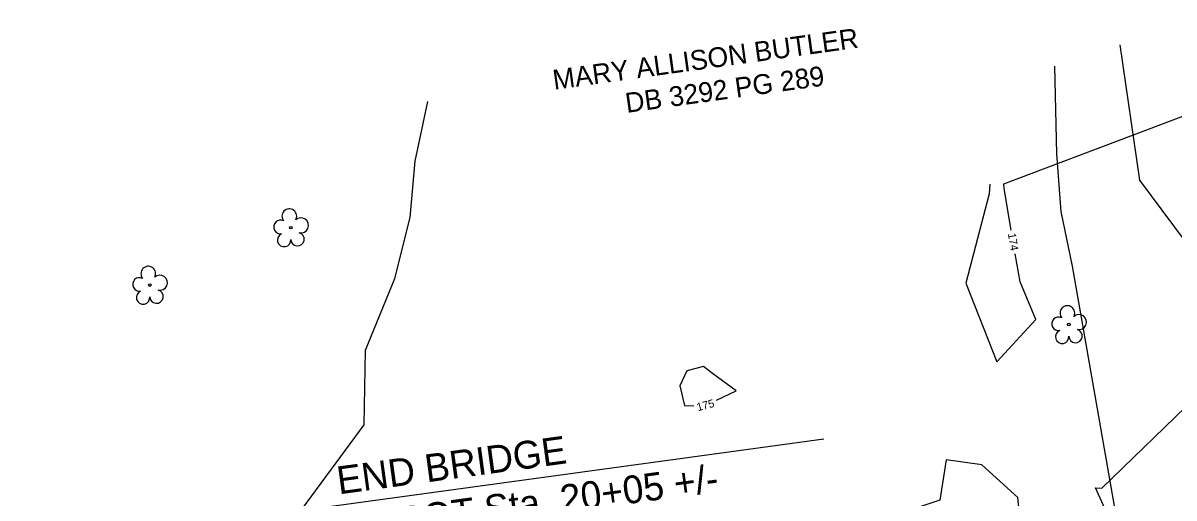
# Model space of a CAD drawing. Extents: x 2086416 to 2115205, y 575507 to 632762.
# Drawn here: x 2112066 to 2112356.1, y 581852.1 to 581971.8 of the extents above; entities that cross this region are included whole.
import ezdxf

# ---------------------------------------------------------------- set-up
doc = ezdxf.new("R2010")
doc.units = 0
for name, color, linetype in [('DTM Contours Major', 7, 'Continuous'), ('DTM Contours Major Text', 7, 'Continuous'), ('DTM Contours Minor', 7, 'Continuous'), ('DTM Contours Minor Text', 7, 'Continuous'), ('Exist Hydro Stream or Body of Water', 7, 'Continuous'), ('Exist Hydro Stream or Body of Water Text', 7, 'Continuous'), ('Exist Property Deed Book Text', 7, 'Continuous'), ('Exist Property Owner Text', 7, 'Continuous'), ('Exist Vegetation Tree CELL', 7, 'Continuous'), ('Exist Vegetation Woods Line', 7, 'Continuous'), ('Prop Horizontal Alignment Station Label', 7, 'Continuous')]:
    doc.layers.add(name, color=color, linetype=linetype)

# ---------------------------------------------------------------- blocks, each defined once
blk = doc.blocks.new('EXIST VEGETATION TREE')
at = {"layer": 'Exist Vegetation Tree CELL'}
blk.add_line((0, 0), (0, 0), dxfattribs=at)
blk.add_circle((0, 0), 0.00652, dxfattribs=at)
for centre, radius, start, end in [((-0.0077, 0.0575), 0.0371, 330.16508, 219.71335), ((-0.0521, 0.0031), 0.0345, 62.66361, 279.3457), ((0.051, 0.0118), 0.038, 257.1011, 134.19993), ((-0.0341, -0.0624), 0.0338, 111.56708, 6.23104), ((0.0335, -0.058), 0.034, 181.28216, 74.55999)]:
    blk.add_arc(centre, radius, start, end, dxfattribs=at)

msp = doc.modelspace()

# ---------------------------------------------------------------- linework, layer by layer
at = {"layer": 'DTM Contours Major'}
for points in [[(2112239.77, 581883.48), (2112237.54, 581885.22), (2112233.31, 581884.15), (2112231.58, 581880.32), (2112232.74, 581875.35), (2112235.11, 581875.27)], [(2112240.76, 581876.76), (2112245.72, 581879.1), (2112239.77, 581883.48)], [(2112307.63, 581860.46), (2112298.69, 581861.68), (2112297.08, 581851.5), (2112289.78, 581849.11), (2112291.03, 581843.54), (2112279.58, 581824.63), (2112299.71, 581826.22), (2112319.48, 581829.38), (2112318.75, 581834.28)], [(2112317.96, 581840.23), (2112316.72, 581852.2), (2112307.63, 581860.46)]]:
    msp.add_lwpolyline(points, dxfattribs=at)
at = {"layer": 'DTM Contours Minor'}
for points in [[(2112315.08, 581919.53), (2112313.29, 581930.07), (2112313.19, 581931.24), (2112370.35, 581952.85)], [(2112309.71, 581931.19), (2112309.53, 581928.69), (2112303.62, 581906.17), (2112311.46, 581886.42), (2112321.28, 581897.08), (2112317.29, 581906.53), (2112316.08, 581913.62)], [(2112254.07, 581816.2), (2112270.16, 581818.14), (2112276.22, 581818.7), (2112299.96, 581821.57), (2112307.56, 581822.62), (2112329.58, 581826.32), (2112343.62, 581828.68), (2112345.41, 581828.91), (2112345.86, 581828.8), (2112351.13, 581828.16), (2112351.3, 581828.82), (2112352.42, 581829.9), (2112349.84, 581834.07), (2112347.16, 581839.69), (2112345.41, 581840.74), (2112341.86, 581842.42), (2112341.8, 581842.53), (2112336.33, 581854.64), (2112337.93, 581854.53), (2112361.72, 581877.6), (2112365.19, 581879.81), (2112375.59, 581882.41), (2112386.63, 581894.46), (2112387.61, 581897.62)]]:
    msp.add_lwpolyline(points, dxfattribs=at)
at = {"layer": 'Exist Hydro Stream or Body of Water'}
for points in [[(2112342.28, 581843.38), (2112330.53, 581910.52), (2112327.68, 581924.24), (2112326.53, 581938.77), (2112326.09, 581960.89)], [(2112117.41, 581823.6), (2112152.01, 581870.55), (2112152.35, 581889.35), (2112159.73, 581907.41), (2112163.61, 581922.72), (2112164.82, 581936.95), (2112168.08, 581951.98)]]:
    msp.add_lwpolyline(points, dxfattribs=at)
at = {"layer": 'Exist Vegetation Woods Line'}
msp.add_lwpolyline([(2112393.84, 581971.76), (2112391.03, 581944.12), (2112388.74, 581921.66), (2112364.61, 581909.13), (2112347.49, 581932.18), (2112342.54, 581966.24)], dxfattribs=at)
at = {"layer": 'Prop Horizontal Alignment Station Label'}
msp.add_line((2112135.81, 581848.95), (2112267.87, 581866.97), dxfattribs=at)

# ---------------------------------------------------------------- block references
at = {"layer": 'Exist Vegetation Tree CELL', "xscale": 50, "yscale": 50}
for p in [(2112133.52, 581920.19), (2112097.98, 581905.73), (2112329.61, 581895.81)]:
    msp.add_blockref('EXIST VEGETATION TREE', p, dxfattribs=at)

# ---------------------------------------------------------------- texts
at = {"layer": 'DTM Contours Major Text'}
msp.add_text('175', height=2, rotation=14.7785, dxfattribs=at).set_placement((2112236.1, 581873.93))
at = {"layer": 'DTM Contours Minor Text'}
msp.add_text('174', height=2, rotation=279.6332, dxfattribs=at).set_placement((2112314.22, 581918.65))
at = {"layer": 'Exist Hydro Stream or Body of Water Text'}
msp.add_text('BLACK RIVER', height=4, rotation=295.5556, dxfattribs=at).set_placement((2112048.15, 581853.78))
at = {"layer": 'Exist Property Deed Book Text'}
msp.add_text('DB 3292 PG 289', height=5, rotation=7.8831, dxfattribs=at).set_placement((2112218.17, 581949.1))
at = {"layer": 'Exist Property Owner Text'}
msp.add_text('MARY ALLISON BUTLER', height=5, rotation=7.883, dxfattribs=at).set_placement((2112199.88, 581954.92))
at = {"layer": 'Prop Horizontal Alignment Station Label'}
for s, p in [('END BRIDGE', (2112145.62, 581852.98)), ('-L- POT Sta. 20+05 +/-  ', (2112147.27, 581840.84))]:
    msp.add_text(s, height=7, rotation=7.771, dxfattribs=at).set_placement(p)

doc.saveas('drawing.dxf')
